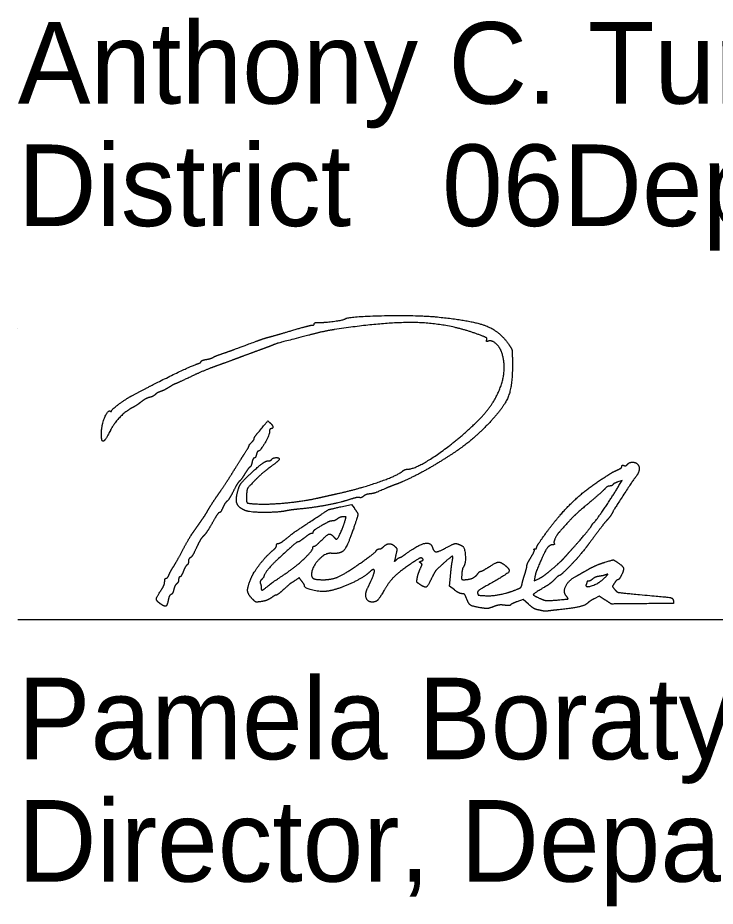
# Model space of a CAD drawing. Extents: x 0 to 34, y 0 to 22.
# Drawn here: x 24.5 to 25.697, y 7.199 to 8.723 of the extents above; entities that cross this region are included whole.
import ezdxf

# ---------------------------------------------------------------- set-up
doc = ezdxf.new("R2010")
doc.units = 0
doc.layers.add('SH_Data', color=7, linetype='Continuous')
doc.layers.add('SH_Text', color=7, linetype='Continuous')

msp = doc.modelspace()

# ---------------------------------------------------------------- linework, layer by layer
at = {"layer": 'SH_Data'}
for p, q in [((24.5, 8.191), (24.5, 8.191)), ((24.5, 7.691), (28, 7.691))]:
    msp.add_line(p, q, dxfattribs=at)
at = {"layer": 'SH_Text'}
for points in [[(25.5318, 7.9205), (25.5372, 7.9294), (25.5298, 7.9268)], [(25.0545, 7.8843), (25.0725, 7.8883), (25.0772, 7.8822)], [(25.2494, 7.7415), (25.2411, 7.7478), (25.2426, 7.7649)], [(25.3874, 7.7635), (25.3864, 7.757), (25.3951, 7.7614)], [(25.5083, 7.7242), (25.4976, 7.731), (25.4892, 7.7264)], [(25.3764, 7.7172), (25.3672, 7.7254), (25.3567, 7.7214)]]:
    msp.add_lwpolyline(points, dxfattribs=at)
for points in [[(25.0179, 8.2007), (25.0275, 8.2004), (25.0585, 8.2047), (25.0619, 8.2069)], [(25.0619, 8.2069), (25.0687, 8.2111), (25.1857, 8.2134), (25.2201, 8.21)], [(25.2201, 8.21), (25.2794, 8.2041), (25.3269, 8.1858), (25.3427, 8.1628)], [(24.9721, 8.1873), (24.9882, 8.192), (25.0031, 8.1959), (25.0051, 8.1959)], [(25.0437, 8.1884), (25.0345, 8.187), (25.0145, 8.1827), (24.9993, 8.1787)], [(25.0051, 8.1959), (25.0072, 8.1959), (25.0089, 8.1971), (25.0089, 8.1984)], [(25.0089, 8.1984), (25.0089, 8.1998), (25.0129, 8.2008), (25.0179, 8.2007)], [(25.2926, 8.1792), (25.242, 8.1982), (25.1341, 8.2022), (25.0437, 8.1884)], [(24.9093, 8.1683), (24.9172, 8.1713), (24.928, 8.1748), (24.9333, 8.1761)], [(24.9333, 8.1761), (24.9386, 8.1775), (24.9561, 8.1825), (24.9721, 8.1873)], [(24.9993, 8.1787), (24.9483, 8.1655), (24.944, 8.1643), (24.9333, 8.1599)], [(25.3049, 8.1706), (25.3059, 8.1731), (25.3024, 8.1755), (25.2926, 8.1792)], [(24.8529, 8.1477), (24.8676, 8.1528), (24.8741, 8.1552), (24.9093, 8.1683)], [(24.9333, 8.1599), (24.9307, 8.1589), (24.9204, 8.1551), (24.9105, 8.1515)], [(25.3073, 8.1685), (25.3047, 8.1675), (25.304, 8.1682), (25.3049, 8.1706)], [(25.3307, 8.1486), (25.3274, 8.1584), (25.313, 8.1707), (25.3073, 8.1685)], [(25.3427, 8.1628), (25.3476, 8.1555), (25.3486, 8.1512), (25.3489, 8.1333)], [(24.8349, 8.1405), (24.8362, 8.1415), (24.8443, 8.1448), (24.8529, 8.1477)], [(24.9105, 8.1515), (24.9006, 8.1479), (24.8855, 8.1423), (24.8769, 8.1391)], [(25.2852, 8.0274), (25.3161, 8.0568), (25.34, 8.1204), (25.3307, 8.1486)], [(24.6969, 8.0755), (24.7271, 8.0918), (24.8007, 8.1274), (24.8091, 8.1299)], [(24.8091, 8.1299), (24.8121, 8.1308), (24.8145, 8.1324), (24.8145, 8.1334)], [(24.8145, 8.1334), (24.8145, 8.1345), (24.8185, 8.1362), (24.8235, 8.1371)], [(24.8235, 8.1371), (24.8284, 8.138), (24.8336, 8.1396), (24.8349, 8.1405)], [(24.8769, 8.1391), (24.8683, 8.1358), (24.8521, 8.1299), (24.8409, 8.1259)], [(25.3489, 8.1333), (25.3496, 8.0926), (25.3335, 8.0529), (25.3041, 8.023)], [(24.8409, 8.1259), (24.8297, 8.1219), (24.8093, 8.1134), (24.7957, 8.1069)], [(24.7957, 8.1069), (24.782, 8.1004), (24.7704, 8.0951), (24.7698, 8.0951)], [(24.745, 8.082), (24.7418, 8.0809), (24.7376, 8.0786), (24.7358, 8.0768)], [(24.7598, 8.0895), (24.7549, 8.0864), (24.7482, 8.083), (24.745, 8.082)], [(24.7698, 8.0951), (24.7693, 8.0951), (24.7648, 8.0926), (24.7598, 8.0895)], [(24.6609, 8.0489), (24.6609, 8.0511), (24.6863, 8.0698), (24.6969, 8.0755)], [(24.7261, 8.072), (24.7226, 8.0711), (24.7159, 8.0675), (24.7113, 8.0639)], [(24.7358, 8.0768), (24.734, 8.075), (24.7297, 8.0728), (24.7261, 8.072)], [(24.6954, 8.0536), (24.685, 8.0482), (24.6651, 8.0274), (24.6589, 8.0153)], [(24.7113, 8.0639), (24.7067, 8.0603), (24.6995, 8.0557), (24.6954, 8.0536)], [(24.6437, 8.0111), (24.6438, 8.0242), (24.6545, 8.0508), (24.6586, 8.0483)], [(24.6586, 8.0483), (24.6599, 8.0475), (24.6609, 8.0478), (24.6609, 8.0489)], [(24.9111, 8.01), (24.9296, 8.0321), (24.9289, 8.0316), (24.933, 8.0282)], [(24.933, 8.0282), (24.9373, 8.0246), (24.9382, 8.0183), (24.9345, 8.0183)], [(25.1685, 7.9487), (25.1826, 7.9487), (25.2507, 7.9946), (25.2852, 8.0274)], [(25.3041, 8.023), (25.2855, 8.0041), (25.2531, 7.9792), (25.2226, 7.9603)], [(24.6451, 7.9973), (24.6443, 7.9981), (24.6437, 8.0043), (24.6437, 8.0111)], [(24.6589, 8.0153), (24.6522, 8.0024), (24.6469, 7.9955), (24.6451, 7.9973)], [(24.9057, 8.0013), (24.9057, 8.0025), (24.9081, 8.0064), (24.9111, 8.01)], [(24.9321, 8.0133), (24.9321, 8.0077), (24.9162, 7.9799), (24.913, 7.9799)], [(24.9345, 8.0183), (24.9332, 8.0183), (24.9321, 8.0161), (24.9321, 8.0133)], [(24.8881, 7.9739), (24.8937, 7.9825), (24.8977, 7.9895), (24.8971, 7.9895)], [(24.8971, 7.9895), (24.8966, 7.9895), (24.8983, 7.9917), (24.9009, 7.9943)], [(24.9009, 7.9943), (24.9035, 7.997), (24.9057, 8.0001), (24.9057, 8.0013)], [(24.913, 7.9799), (24.9119, 7.9799), (24.9103, 7.9772), (24.9095, 7.9739)], [(24.8661, 7.9389), (24.8727, 7.9495), (24.8826, 7.9653), (24.8881, 7.9739)], [(24.8973, 7.939), (24.913, 7.9536), (24.9258, 7.9631), (24.9297, 7.9631)], [(24.9021, 7.9608), (24.9012, 7.9568), (24.8995, 7.953), (24.8982, 7.9522)], [(24.9058, 7.9679), (24.9047, 7.9679), (24.903, 7.9647), (24.9021, 7.9608)], [(24.9095, 7.9739), (24.9087, 7.9706), (24.907, 7.9679), (24.9058, 7.9679)], [(24.9297, 7.9631), (24.9322, 7.9631), (24.9349, 7.9642), (24.9357, 7.9655)], [(24.9489, 7.9659), (24.9489, 7.9648), (24.9421, 7.9589), (24.9339, 7.9528)], [(24.9357, 7.9655), (24.9375, 7.9684), (24.9489, 7.9688), (24.9489, 7.9659)], [(25.2226, 7.9603), (25.2035, 7.9485), (25.1622, 7.9275), (25.1481, 7.9224)], [(25.5466, 7.9573), (25.5482, 7.9592), (25.5519, 7.9607), (25.5548, 7.9607)], [(25.5548, 7.9607), (25.5643, 7.9607), (25.568, 7.9447), (25.5606, 7.9357)], [(24.8982, 7.9522), (24.8969, 7.9514), (24.8931, 7.9462), (24.8897, 7.9407)], [(24.9339, 7.9528), (24.9256, 7.9467), (24.9131, 7.9358), (24.9061, 7.9287)], [(25.0485, 7.9068), (25.0854, 7.915), (25.1517, 7.9379), (25.1603, 7.9454)], [(25.1603, 7.9454), (25.1624, 7.9472), (25.1661, 7.9487), (25.1685, 7.9487)], [(25.5001, 7.9304), (25.5191, 7.9426), (25.5209, 7.9437), (25.5291, 7.9474)], [(25.5291, 7.9474), (25.5334, 7.9493), (25.5369, 7.9521), (25.5369, 7.9537)], [(25.5369, 7.9537), (25.5369, 7.9552), (25.5384, 7.9559), (25.5403, 7.9551)], [(25.5403, 7.9551), (25.5422, 7.9544), (25.545, 7.9554), (25.5466, 7.9573)], [(24.8443, 7.9059), (24.8497, 7.9134), (24.8595, 7.9282), (24.8661, 7.9389)], [(24.876, 7.9043), (24.8787, 7.9174), (24.8849, 7.9274), (24.8973, 7.939)], [(24.8897, 7.9407), (24.8863, 7.9352), (24.8822, 7.9296), (24.8806, 7.9283)], [(24.9061, 7.9287), (24.8954, 7.9177), (24.8932, 7.914), (24.8927, 7.9058)], [(25.4055, 7.8378), (25.4278, 7.8686), (25.4728, 7.9127), (25.5001, 7.9304)], [(25.5606, 7.9357), (25.5564, 7.9307), (25.5236, 7.8802), (25.5204, 7.8741)], [(24.8806, 7.9283), (24.8789, 7.927), (24.8742, 7.9194), (24.8702, 7.9114)], [(25.1325, 7.9162), (25.1154, 7.9088), (25.1105, 7.9071), (25.1039, 7.9063)], [(25.1481, 7.9224), (25.1435, 7.9207), (25.1364, 7.918), (25.1325, 7.9162)], [(25.507, 7.9145), (25.5043, 7.9116), (25.4918, 7.9005), (25.4793, 7.89)], [(25.489, 7.8575), (25.4918, 7.8595), (25.52, 7.901), (25.5318, 7.9205)], [(25.5158, 7.9199), (25.5136, 7.9199), (25.5097, 7.9175), (25.507, 7.9145)], [(25.5212, 7.9221), (25.5204, 7.9209), (25.518, 7.9199), (25.5158, 7.9199)], [(25.5298, 7.9268), (25.5258, 7.9254), (25.5219, 7.9233), (25.5212, 7.9221)], [(24.8276, 7.8803), (24.8315, 7.8869), (24.839, 7.8985), (24.8443, 7.9059)], [(24.8702, 7.9114), (24.8662, 7.9034), (24.8611, 7.8954), (24.859, 7.8936)], [(24.8913, 7.8775), (24.8809, 7.8814), (24.8737, 7.8938), (24.876, 7.9043)], [(24.8927, 7.9058), (24.8918, 7.8923), (24.8959, 7.8895), (24.9165, 7.8889)], [(24.9165, 7.8889), (24.9358, 7.8884), (24.9936, 7.8945), (25.0149, 7.8993)], [(25.0149, 7.8993), (25.0228, 7.9011), (25.0379, 7.9045), (25.0485, 7.9068)], [(25.0863, 7.9001), (25.0846, 7.9007), (25.0765, 7.899), (25.0683, 7.8963)], [(25.0931, 7.9022), (25.091, 7.9004), (25.0879, 7.8995), (25.0863, 7.9001)], [(25.1039, 7.9063), (25.1, 7.9059), (25.0952, 7.9041), (25.0931, 7.9022)], [(24.859, 7.8936), (24.8568, 7.8918), (24.8535, 7.8867), (24.8517, 7.8823)], [(25.0683, 7.8963), (25.0518, 7.891), (25.0067, 7.8826), (24.9829, 7.8803)], [(25.0005, 7.8579), (25.0322, 7.8789), (25.0335, 7.8796), (25.0545, 7.8843)], [(25.4793, 7.89), (25.4597, 7.8734), (25.448, 7.862), (25.4313, 7.8432)], [(24.8146, 7.8597), (24.8179, 7.8645), (24.8238, 7.8737), (24.8276, 7.8803)], [(24.846, 7.8743), (24.8447, 7.8743), (24.8393, 7.8664), (24.8339, 7.8568)], [(24.8517, 7.8823), (24.8498, 7.8779), (24.8473, 7.8743), (24.846, 7.8743)], [(24.9625, 7.8776), (24.9488, 7.8746), (24.8993, 7.8745), (24.8913, 7.8775)], [(24.9829, 7.8803), (24.9746, 7.8795), (24.9654, 7.8783), (24.9625, 7.8776)], [(25.0772, 7.8822), (25.0838, 7.8734), (25.0836, 7.8685), (25.0759, 7.846)], [(25.5204, 7.8741), (25.5187, 7.8706), (25.5148, 7.8652), (25.5118, 7.8619)], [(24.801, 7.8405), (24.8051, 7.8463), (24.8112, 7.8549), (24.8146, 7.8597)], [(24.8339, 7.8568), (24.8286, 7.8471), (24.8219, 7.8371), (24.8191, 7.8346)], [(24.9613, 7.83), (24.975, 7.841), (24.973, 7.8396), (25.0005, 7.8579)], [(25.0302, 7.8568), (25.0158, 7.8489), (25.0065, 7.8425), (25.0065, 7.8405)], [(25.0399, 7.8599), (25.0377, 7.8599), (25.0333, 7.8585), (25.0302, 7.8568)], [(25.0486, 7.8635), (25.0461, 7.8615), (25.0421, 7.8599), (25.0399, 7.8599)], [(25.0471, 7.8287), (25.0489, 7.8287), (25.0587, 7.8499), (25.0618, 7.8605)], [(25.0585, 7.8671), (25.0557, 7.867), (25.0512, 7.8654), (25.0486, 7.8635)], [(25.0618, 7.8605), (25.0635, 7.8663), (25.0631, 7.8671), (25.0585, 7.8671)], [(25.4538, 7.8146), (25.4691, 7.8317), (25.4827, 7.8481), (25.4851, 7.8524)], [(25.4851, 7.8524), (25.4863, 7.8546), (25.4881, 7.8569), (25.489, 7.8575)], [(25.5118, 7.8619), (25.5088, 7.8587), (25.4999, 7.8474), (25.492, 7.8367)], [(24.7821, 7.8083), (24.7884, 7.8202), (24.7969, 7.8347), (24.801, 7.8405)], [(25.0038, 7.8383), (25.0024, 7.8383), (24.9971, 7.8351), (24.9921, 7.8311)], [(25.0065, 7.8405), (25.0065, 7.8393), (25.0053, 7.8383), (25.0038, 7.8383)], [(25.0209, 7.8263), (25.031, 7.8365), (25.0376, 7.8383), (25.0425, 7.8323)], [(25.0759, 7.846), (25.0656, 7.8161), (25.0537, 7.803), (25.0377, 7.8044)], [(25.3905, 7.8145), (25.3905, 7.8159), (25.3972, 7.8264), (25.4055, 7.8378)], [(25.4313, 7.8432), (25.4255, 7.8366), (25.4192, 7.8237), (25.4206, 7.8213)], [(24.8191, 7.8346), (24.8162, 7.832), (24.8107, 7.8229), (24.8068, 7.8143)], [(24.981, 7.8239), (24.9791, 7.8239), (24.9706, 7.8167), (24.9453, 7.7934)], [(24.9475, 7.8215), (24.9493, 7.8215), (24.9555, 7.8253), (24.9613, 7.83)], [(24.9921, 7.8311), (24.9871, 7.8272), (24.9821, 7.8239), (24.981, 7.8239)], [(25.0089, 7.8167), (25.0102, 7.8167), (25.0156, 7.8211), (25.0209, 7.8263)], [(25.0425, 7.8323), (25.0441, 7.8304), (25.0462, 7.8287), (25.0471, 7.8287)], [(25.1657, 7.8033), (25.1859, 7.8184), (25.2086, 7.824), (25.2116, 7.8146)], [(25.492, 7.8367), (25.4841, 7.8261), (25.4765, 7.8159), (25.475, 7.814)], [(24.7667, 7.7807), (24.7689, 7.784), (24.7759, 7.7965), (24.7821, 7.8083)], [(24.8068, 7.8143), (24.8029, 7.8058), (24.7981, 7.7979), (24.7963, 7.7968)], [(24.9006, 7.7621), (24.9051, 7.7725), (24.9283, 7.802), (24.9387, 7.8103)], [(24.9387, 7.8103), (24.9417, 7.8127), (24.9441, 7.8162), (24.9441, 7.8181)], [(24.9441, 7.8181), (24.9441, 7.82), (24.9456, 7.8215), (24.9475, 7.8215)], [(24.9604, 7.7702), (24.976, 7.7806), (25.0065, 7.8093), (25.0065, 7.8136)], [(25.0065, 7.8136), (25.0065, 7.8153), (25.0076, 7.8167), (25.0089, 7.8167)], [(25.0725, 7.7771), (25.0911, 7.7894), (25.1135, 7.8061), (25.1152, 7.8089)], [(25.1152, 7.8089), (25.1163, 7.8106), (25.1186, 7.8119), (25.1204, 7.8119)], [(25.1204, 7.8119), (25.1223, 7.8119), (25.1255, 7.8137), (25.1277, 7.8158)], [(25.1277, 7.8158), (25.1326, 7.8208), (25.1426, 7.8209), (25.1475, 7.8159)], [(25.1475, 7.8159), (25.1507, 7.8128), (25.1509, 7.8103), (25.1488, 7.8011)], [(25.2116, 7.8146), (25.214, 7.807), (25.2221, 7.8069), (25.2354, 7.8142)], [(25.2354, 7.8142), (25.2474, 7.8208), (25.2546, 7.8216), (25.2628, 7.817)], [(25.2628, 7.817), (25.2672, 7.8145), (25.2689, 7.7865), (25.265, 7.7813)], [(25.3807, 7.7976), (25.3846, 7.8039), (25.3871, 7.8097), (25.3863, 7.8105)], [(25.3863, 7.8105), (25.3855, 7.8113), (25.3862, 7.8119), (25.3877, 7.8119)], [(25.3877, 7.8119), (25.3892, 7.8119), (25.3905, 7.8131), (25.3905, 7.8145)], [(25.4184, 7.8191), (25.412, 7.8191), (25.4025, 7.804), (25.3904, 7.7747)], [(25.4206, 7.8213), (25.4214, 7.8201), (25.4204, 7.8191), (25.4184, 7.8191)], [(25.4382, 7.7971), (25.4413, 7.8006), (25.4484, 7.8085), (25.4538, 7.8146)], [(25.475, 7.814), (25.4617, 7.7976), (25.4572, 7.7925), (25.4453, 7.7803)], [(24.7963, 7.7968), (24.7944, 7.7958), (24.7929, 7.7929), (24.7929, 7.7904)], [(24.9453, 7.7934), (24.9362, 7.785), (24.9225, 7.768), (24.9225, 7.765)], [(25.0377, 7.8044), (25.0273, 7.8053), (25.0041, 7.7799), (25.0041, 7.7676)], [(25.1488, 7.8011), (25.1465, 7.7909), (25.1466, 7.7904), (25.1504, 7.7939)], [(25.1504, 7.7939), (25.1526, 7.7959), (25.1553, 7.7975), (25.1562, 7.7975)], [(25.1562, 7.7975), (25.1572, 7.7975), (25.1615, 7.8001), (25.1657, 7.8033)], [(25.1943, 7.7955), (25.1925, 7.7973), (25.1866, 7.7945), (25.1741, 7.786)], [(25.1915, 7.7878), (25.1893, 7.7892), (25.1896, 7.7901), (25.1927, 7.7913)], [(25.1927, 7.7913), (25.1957, 7.7924), (25.1962, 7.7936), (25.1943, 7.7955)], [(25.2354, 7.7914), (25.2195, 7.7774), (25.2158, 7.773), (25.2103, 7.7616)], [(25.2455, 7.7897), (25.2474, 7.7992), (25.2447, 7.7996), (25.2354, 7.7914)], [(25.3737, 7.7829), (25.3737, 7.7847), (25.3769, 7.7914), (25.3807, 7.7976)], [(25.4181, 7.7783), (25.426, 7.7851), (25.4351, 7.7936), (25.4382, 7.7971)], [(25.5074, 7.789), (25.5215, 7.7932), (25.5226, 7.7932), (25.5285, 7.7894)], [(24.7598, 7.7681), (24.7614, 7.7718), (24.7645, 7.7774), (24.7667, 7.7807)], [(24.7904, 7.7843), (24.789, 7.7834), (24.7862, 7.7785), (24.7841, 7.7733)], [(24.7929, 7.7904), (24.7929, 7.7879), (24.7918, 7.7851), (24.7904, 7.7843)], [(25.024, 7.7591), (25.0371, 7.7591), (25.0562, 7.7662), (25.0725, 7.7771)], [(25.1121, 7.7738), (25.1121, 7.7769), (25.1081, 7.7764), (25.1045, 7.7729)], [(25.1741, 7.786), (25.1544, 7.7726), (25.1372, 7.7555), (25.1289, 7.7411)], [(25.1857, 7.7623), (25.1865, 7.7665), (25.1888, 7.7736), (25.1908, 7.778)], [(25.1908, 7.778), (25.1937, 7.7842), (25.1938, 7.7864), (25.1915, 7.7878)], [(25.2426, 7.7649), (25.2434, 7.7743), (25.2447, 7.7854), (25.2455, 7.7897)], [(25.265, 7.7813), (25.2637, 7.7797), (25.2624, 7.774), (25.262, 7.7687)], [(25.2945, 7.7735), (25.2957, 7.7735), (25.3018, 7.7768), (25.3081, 7.7807)], [(25.3363, 7.7837), (25.346, 7.7761), (25.3391, 7.7682), (25.3076, 7.7505)], [(25.3081, 7.7807), (25.321, 7.789), (25.3286, 7.7898), (25.3363, 7.7837)], [(25.3702, 7.7687), (25.3721, 7.7747), (25.3737, 7.781), (25.3737, 7.7829)], [(25.3951, 7.7614), (25.3998, 7.7639), (25.4102, 7.7715), (25.4181, 7.7783)], [(25.4453, 7.7803), (25.4378, 7.7726), (25.4308, 7.7663), (25.4297, 7.7663)], [(25.4585, 7.7653), (25.4614, 7.7668), (25.4702, 7.7718), (25.4781, 7.7763)], [(25.4781, 7.7763), (25.486, 7.7808), (25.4992, 7.7865), (25.5074, 7.789)], [(25.5285, 7.7894), (25.5381, 7.7831), (25.5405, 7.7757), (25.5359, 7.7667)], [(24.7521, 7.7559), (24.7521, 7.759), (24.7532, 7.7615), (24.7545, 7.7615)], [(24.7545, 7.7615), (24.7559, 7.7615), (24.7583, 7.7645), (24.7598, 7.7681)], [(24.7782, 7.7639), (24.7771, 7.7639), (24.7761, 7.7619), (24.7761, 7.7594)], [(24.7841, 7.7733), (24.7821, 7.7682), (24.7794, 7.7639), (24.7782, 7.7639)], [(24.9023, 7.7264), (24.8947, 7.734), (24.8941, 7.7468), (24.9006, 7.7621)], [(24.9225, 7.765), (24.9225, 7.7642), (24.9208, 7.7619), (24.9188, 7.7599)], [(24.9289, 7.7478), (24.9364, 7.7539), (24.9417, 7.7576), (24.9604, 7.7702)], [(24.9875, 7.7566), (24.983, 7.7624), (24.983, 7.7624), (24.9762, 7.758)], [(25.0041, 7.7676), (25.0041, 7.7625), (25.0119, 7.7591), (25.024, 7.7591)], [(25.1045, 7.7729), (25.0949, 7.7638), (25.0562, 7.745), (25.0377, 7.7405)], [(25.1015, 7.7471), (25.1056, 7.7548), (25.1121, 7.7711), (25.1121, 7.7738)], [(25.1903, 7.7508), (25.1853, 7.7541), (25.1845, 7.7561), (25.1857, 7.7623)], [(25.2103, 7.7616), (25.2036, 7.7479), (25.1988, 7.7453), (25.1903, 7.7508)], [(25.262, 7.7687), (25.2615, 7.7612), (25.2622, 7.7591), (25.2654, 7.7591)], [(25.2654, 7.7591), (25.2737, 7.7591), (25.2857, 7.764), (25.289, 7.7687)], [(25.289, 7.7687), (25.2908, 7.7713), (25.2933, 7.7735), (25.2945, 7.7735)], [(25.3654, 7.7517), (25.3661, 7.7551), (25.3683, 7.7628), (25.3702, 7.7687)], [(25.3904, 7.7747), (25.3893, 7.7721), (25.388, 7.767), (25.3874, 7.7635)], [(25.4297, 7.7663), (25.4286, 7.7663), (25.4247, 7.7632), (25.4211, 7.7594)], [(25.4415, 7.7309), (25.4354, 7.7383), (25.4452, 7.7581), (25.4585, 7.7653)], [(25.4755, 7.751), (25.473, 7.7445), (25.4984, 7.7534), (25.5069, 7.7621)], [(25.4975, 7.7649), (25.4936, 7.7644), (25.4887, 7.7623), (25.4865, 7.7603)], [(25.5093, 7.7676), (25.5067, 7.7666), (25.5013, 7.7654), (25.4975, 7.7649)], [(25.5069, 7.7621), (25.5124, 7.7676), (25.513, 7.769), (25.5093, 7.7676)], [(25.5359, 7.7667), (25.5337, 7.7625), (25.531, 7.7591), (25.5299, 7.7591)], [(24.7463, 7.7416), (24.7495, 7.7464), (24.7521, 7.7528), (24.7521, 7.7559)], [(24.7727, 7.7521), (24.7708, 7.7505), (24.7685, 7.746), (24.7676, 7.742)], [(24.7761, 7.7594), (24.7761, 7.757), (24.7745, 7.7536), (24.7727, 7.7521)], [(24.9188, 7.7599), (24.9167, 7.7578), (24.9156, 7.7546), (24.9164, 7.7526)], [(24.9164, 7.7526), (24.9171, 7.7507), (24.9177, 7.7476), (24.9177, 7.7457)], [(24.9177, 7.7457), (24.9177, 7.7409), (24.9211, 7.7415), (24.9289, 7.7478)], [(24.9762, 7.758), (24.968, 7.7526), (24.9654, 7.7506), (24.9542, 7.7405)], [(24.992, 7.7492), (24.992, 7.75), (24.99, 7.7534), (24.9875, 7.7566)], [(25.0377, 7.7405), (25.0248, 7.7374), (24.9922, 7.7436), (24.992, 7.7492)], [(25.1082, 7.7207), (25.0998, 7.7207), (25.0958, 7.7365), (25.1015, 7.7471)], [(25.3076, 7.7505), (25.2943, 7.743), (25.2881, 7.7382), (25.289, 7.736)], [(25.3527, 7.741), (25.3615, 7.7444), (25.3645, 7.7469), (25.3654, 7.7517)], [(25.4031, 7.7458), (25.3852, 7.7354), (25.3842, 7.7321), (25.3971, 7.7266)], [(25.4211, 7.7594), (25.4175, 7.7556), (25.4094, 7.7494), (25.4031, 7.7458)], [(25.4769, 7.7557), (25.4769, 7.7552), (25.4763, 7.7531), (25.4755, 7.751)], [(25.4797, 7.7567), (25.4782, 7.7567), (25.4769, 7.7563), (25.4769, 7.7557)], [(25.4865, 7.7603), (25.4843, 7.7584), (25.4813, 7.7567), (25.4797, 7.7567)], [(25.524, 7.7533), (25.5205, 7.748), (25.5206, 7.7471), (25.5244, 7.7424)], [(25.5299, 7.7591), (25.5288, 7.7591), (25.5261, 7.7565), (25.524, 7.7533)], [(24.7446, 7.7179), (24.7376, 7.7228), (24.7381, 7.7295), (24.7463, 7.7416)], [(24.7629, 7.7336), (24.7612, 7.7329), (24.7591, 7.7288), (24.7583, 7.7244)], [(24.7676, 7.742), (24.7668, 7.7381), (24.7646, 7.7343), (24.7629, 7.7336)], [(24.9435, 7.7327), (24.9424, 7.7327), (24.9386, 7.7306), (24.935, 7.728)], [(24.9542, 7.7405), (24.9494, 7.7362), (24.9446, 7.7327), (24.9435, 7.7327)], [(25.1289, 7.7411), (25.1207, 7.727), (25.1143, 7.7207), (25.1082, 7.7207)], [(25.2624, 7.7351), (25.2599, 7.7351), (25.254, 7.738), (25.2494, 7.7415)], [(25.27, 7.7273), (25.2681, 7.7325), (25.2656, 7.7351), (25.2624, 7.7351)], [(25.289, 7.736), (25.2903, 7.7326), (25.291, 7.7324), (25.3029, 7.7317)], [(25.3029, 7.7317), (25.3134, 7.7311), (25.3396, 7.736), (25.3527, 7.741)], [(25.4239, 7.7241), (25.4434, 7.7257), (25.4452, 7.7264), (25.4415, 7.7309)], [(25.5244, 7.7424), (25.528, 7.7379), (25.533, 7.7368), (25.5669, 7.7337)], [(25.5669, 7.7337), (25.616, 7.7292), (25.6243, 7.7276), (25.6252, 7.7228)], [(24.7583, 7.7244), (24.7564, 7.7146), (24.7522, 7.7127), (24.7446, 7.7179)], [(24.9185, 7.7217), (24.9098, 7.7204), (24.9076, 7.721), (24.9023, 7.7264)], [(24.935, 7.728), (24.9314, 7.7254), (24.924, 7.7226), (24.9185, 7.7217)], [(25.2953, 7.7108), (25.2803, 7.7132), (25.2735, 7.7177), (25.27, 7.7273)], [(25.3353, 7.7153), (25.3295, 7.7161), (25.3222, 7.7151), (25.3164, 7.7128)], [(25.3454, 7.7156), (25.345, 7.7148), (25.3404, 7.7146), (25.3353, 7.7153)], [(25.3567, 7.7214), (25.3509, 7.7191), (25.3458, 7.7165), (25.3454, 7.7156)], [(25.391, 7.7077), (25.388, 7.7083), (25.3814, 7.7126), (25.3764, 7.7172)], [(25.3971, 7.7266), (25.4039, 7.7236), (25.4104, 7.723), (25.4239, 7.7241)], [(25.4775, 7.7186), (25.4738, 7.7149), (25.4523, 7.71), (25.4289, 7.7076)], [(25.4892, 7.7264), (25.4846, 7.724), (25.4794, 7.7204), (25.4775, 7.7186)], [(25.5549, 7.7177), (25.5192, 7.7174), (25.5188, 7.7174), (25.5083, 7.7242)], [(25.6252, 7.7228), (25.626, 7.7186), (25.624, 7.7185), (25.5549, 7.7177)], [(25.3164, 7.7128), (25.3094, 7.71), (25.3039, 7.7094), (25.2953, 7.7108)], [(25.4013, 7.7055), (25.3987, 7.7061), (25.394, 7.7071), (25.391, 7.7077)], [(25.4097, 7.7053), (25.4077, 7.7049), (25.4039, 7.705), (25.4013, 7.7055)], [(25.4289, 7.7076), (25.4203, 7.7067), (25.4117, 7.7057), (25.4097, 7.7053)]]:
    msp.add_open_spline(points, degree=2, dxfattribs=at)

# ---------------------------------------------------------------- texts
for s, p in [('Anthony C. Turowski, P.E.', (24.5, 8.576)), ('District       Deputy Director', (24.5, 8.366)), ('              06', (24.5, 8.366)), ('Pamela Boratyn', (24.5, 7.451)), ('Director, Department of Transportation', (24.5, 7.241))]:
    msp.add_text(s, height=0.14, dxfattribs=at).set_placement(p)

doc.saveas('drawing.dxf')
